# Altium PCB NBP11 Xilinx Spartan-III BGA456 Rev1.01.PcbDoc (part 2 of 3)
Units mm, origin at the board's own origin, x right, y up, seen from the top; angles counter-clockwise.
Board outline 69 x 80.99 mm, 6 copper layers (Top Layer, MidLayer1, InternalPlane1, InternalPlane2, MidLayer2, Bottom Layer); 105 components, 277 nets, 967 pads, 559 vias.
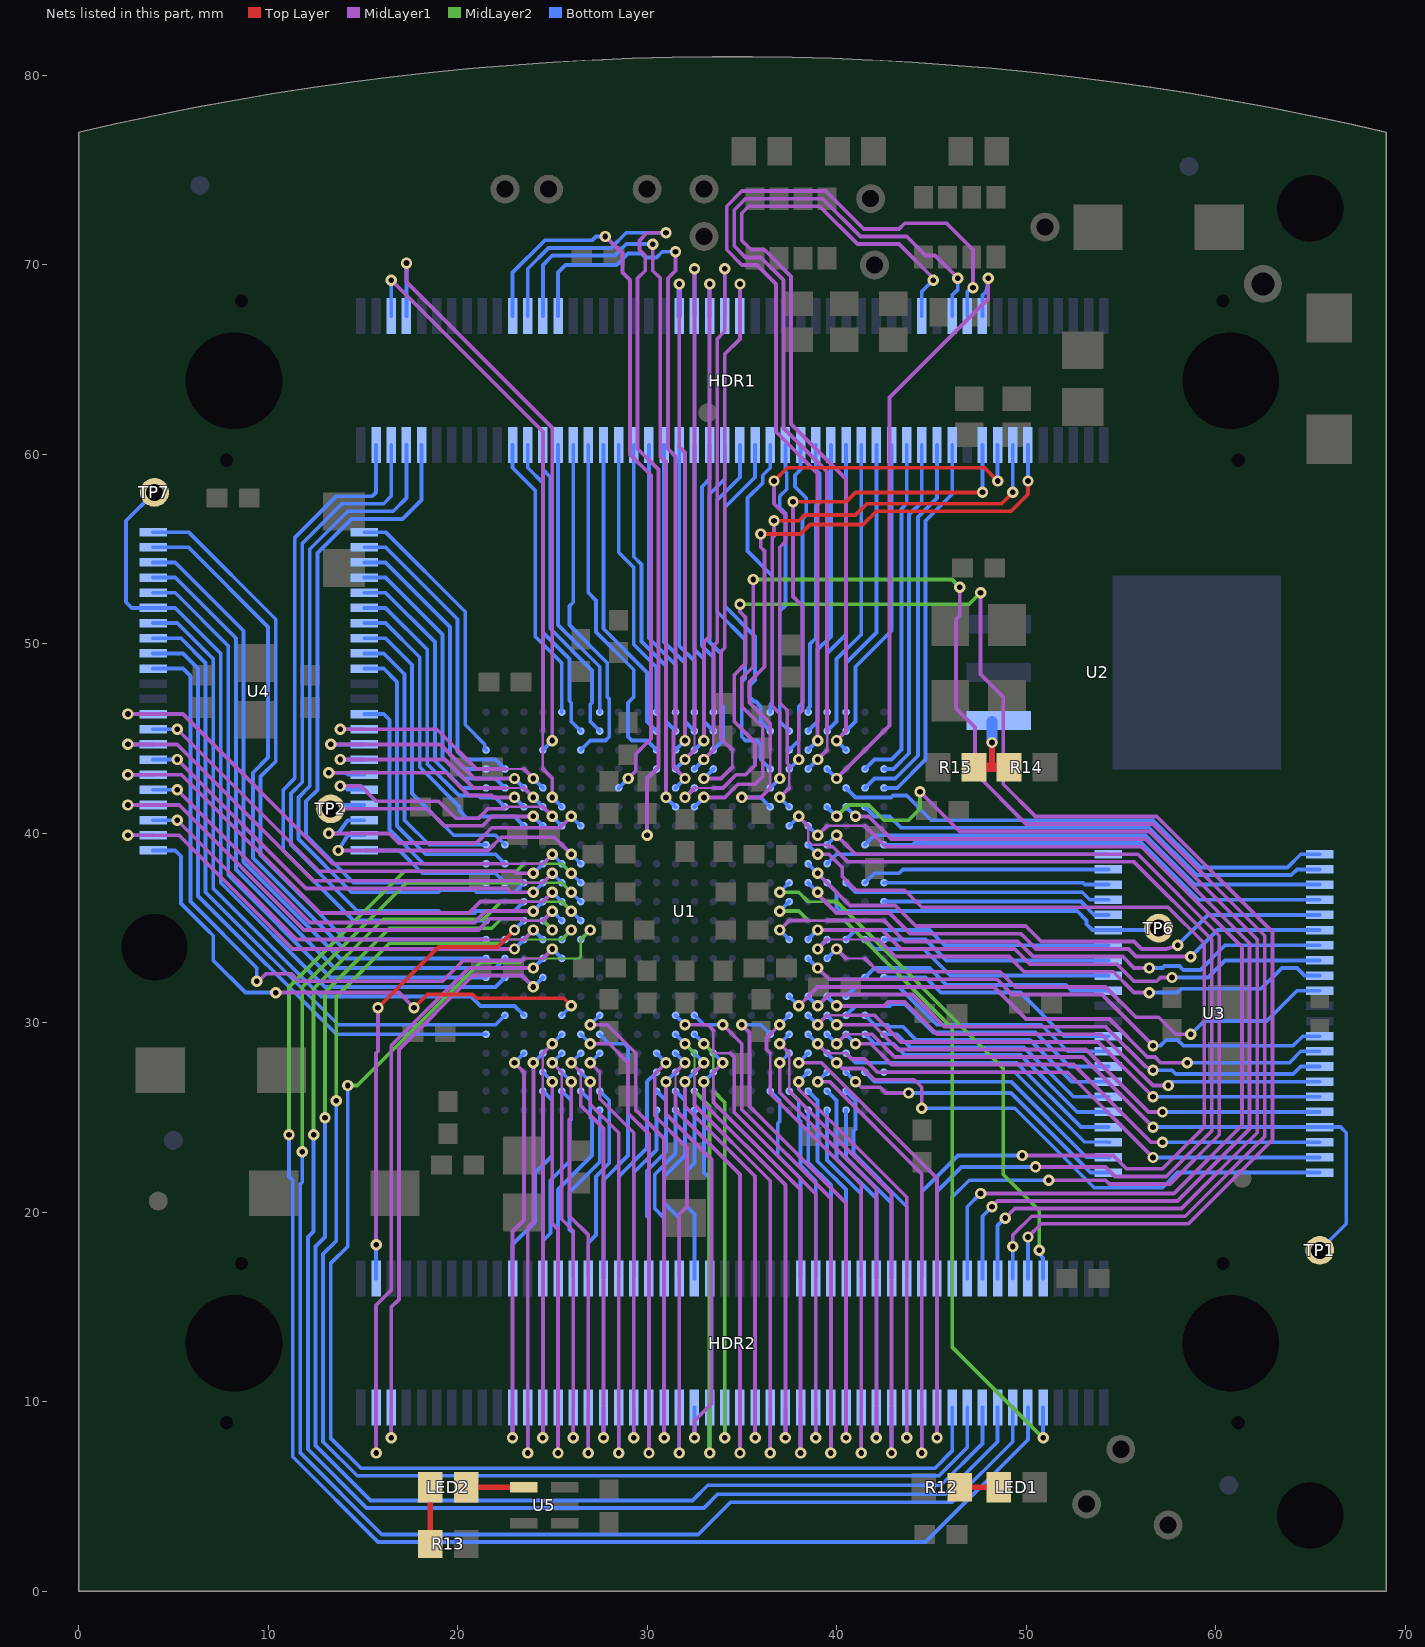
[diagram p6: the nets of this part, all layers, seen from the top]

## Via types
v1: diameter 0.6, hole 0.3, Top Layer to Bottom Layer, tented both sides, 480 vias
v2: diameter 2, hole 1.2, Top Layer to Bottom Layer, tented both sides, 42 vias
v3: diameter 0.9, hole 0.5, Top Layer to Bottom Layer, tented both sides, 33 vias
v4: diameter 0.8, hole 0.5, Top Layer to Bottom Layer, tented both sides, 2 vias
v5: diameter 1.3, hole 0.9, Top Layer to Bottom Layer, tented both sides, 1 vias
v6: diameter 1.8, hole 0.9, Top Layer to Bottom Layer, tented both sides, 1 vias

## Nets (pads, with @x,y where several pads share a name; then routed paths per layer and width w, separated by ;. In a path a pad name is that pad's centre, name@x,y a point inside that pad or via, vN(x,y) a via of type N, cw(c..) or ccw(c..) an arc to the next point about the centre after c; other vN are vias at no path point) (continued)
IO7: HDR2.21 U1.C19 | length 22.6
  MidLayer1 w0.2: v1(22.9,8.1) 22.9,19 23.5,19.6 23.5,27.4 v1(23,27.9)
  Bottom Layer w0.2: v1(22.9,8.1) HDR2.21@22.9,9.7 ; v1(23,27.9) U1.C19@23.5,28.4
IO8: HDR2.23 U1.D19 | length 23.8
  MidLayer1 w0.2: v1(23.7,7.3) 23.7,19.2 24,19.5 v1(24,27.9)
  Bottom Layer w0.2: v1(23.7,7.3) HDR2.23@23.7,9.7 ; v1(24,27.9) U1.D19@24.5,28.4
IO9: HDR2.25 U1.E18 | length 23.3
  MidLayer1 w0.127: 24.5,26.4 24.5,28.4
  MidLayer1 w0.2: v1(24.5,8.1) 24.5,26.4 ; 24.5,28.4 v1(25,28.9)
  Bottom Layer w0.2: v1(24.5,8.1) HDR2.25@24.5,9.7 ; v1(25,28.9) U1.E18@25.5,29.4
IO10: HDR2.27 U1.D20 | length 22.8
  MidLayer1 w0.2: v1(25,26.9) 25,19.4 25.3,19.1 v1(25.3,7.3)
  Bottom Layer w0.2: U1.D20@24.5,27.4 v1(25,26.9) ; v1(25.3,7.3) HDR2.27@25.3,9.7
IO11: HDR2.29 U1.E19 | length 22.6
  MidLayer1 w0.127: 25.5,26.4 25.5,27.4
  MidLayer1 w0.2: v1(25,27.9) 25.5,27.4 ; 25.5,26.4 25.5,19.634 26.1,19.034 v1(26.1,8.1)
  Bottom Layer w0.2: v1(25,27.9) U1.E19@25.5,28.4 ; v1(26.1,8.1) HDR2.29@26.1,9.7
IO12: HDR2.31 U1.E20 | length 23.2
  MidLayer1 w0.2: v1(26,26.9) 26,25 25.9,24.9 25.9,19.8 26.9,18.8 v1(26.9,7.3)
  Bottom Layer w0.2: U1.E20@25.5,27.4 v1(26,26.9) ; v1(26.9,7.3) HDR2.31@26.9,9.7
IO13: HDR2.33 U1.F19 | length 22.8
  MidLayer1 w0.127: 26.5,26.4 26.5,27.4
  MidLayer1 w0.2: v1(26,27.9) 26.5,27.4 ; 26.5,26.4 26.5,25.634 27.7,24.434 v1(27.7,8.1)
  Bottom Layer w0.2: v1(26,27.9) U1.F19@26.5,28.4 ; v1(27.7,8.1) HDR2.33@27.7,9.7
IO14: HDR2.35 U1.F20 | length 23.3
  MidLayer1 w0.2: v1(27,26.9) 27,25.7 28.5,24.2 v1(28.5,7.3)
  Bottom Layer w0.2: U1.F20@26.5,27.4 v1(27,26.9) ; v1(28.5,7.3) HDR2.35@28.5,9.7
IO15: HDR2.37 U1.G19 | length 23.1
  MidLayer1 w0.127: 27.5,26.4 27.5,27.4
  MidLayer1 w0.2: v1(27,27.9) 27.5,27.4 ; 27.5,26.4 27.5,26 29.3,24.2 v1(29.3,8.1)
  Bottom Layer w0.2: v1(27,27.9) U1.G19@27.5,28.4 ; v1(29.3,8.1) HDR2.37@29.3,9.7
IO16: HDR2.39 U1.F18 | length 26.6
  MidLayer1 w0.2: v1(27,28.9) 28,28.9 29,27.9 29,25.234 30.1,24.134 v1(30.1,7.3)
  Bottom Layer w0.2: U1.F18@26.5,29.4 v1(27,28.9) ; v1(30.1,7.3) HDR2.39@30.1,9.7
IO17: HDR2.41 U1.G17 | length 26.2
  MidLayer1 w0.2: v1(27,29.9) 27.9,29.9 29.4,28.4 29.4,25.4 30.9,23.9 v1(30.9,8.1)
  Bottom Layer w0.2: v1(27,29.9) U1.G17@27.5,30.4 ; v1(30.9,8.1) HDR2.41@30.9,9.7
IO18: HDR2.43 U1.K19 | length 24.8
  MidLayer1 w0.2: v1(31,27.9) 30.4,27.3 30.4,25.1 32.1,23.4 32.1,20.3 31.7,19.9 v1(31.7,7.3)
  Bottom Layer w0.2: U1.K19@30.5,28.4 v1(31,27.9) ; v1(31.7,7.3) HDR2.43@31.7,9.7
IO19: HDR2.45 U1.L20 | length 22.5
  MidLayer1 w0.2: v1(31,26.9) 31,25.2 33.4,22.8 33.4,9.9 32.5,9 v1(32.5,8.1)
  Bottom Layer w0.2: v1(31,26.9) U1.L20@31.5,27.4 ; v1(32.5,8.1) HDR2.45@32.5,9.7
IO20: HDR2.47 U1.L18 | length 25.2
  MidLayer2 w0.127: 32.5,26.4 32.5,28.4
  MidLayer2 w0.2: v1(32,28.9) 32.5,28.4 ; 32.5,26.4 33.3,25.6 v1(33.3,7.3)
  Bottom Layer w0.2: U1.L18@31.5,29.4 v1(32,28.9) ; v1(33.3,7.3) HDR2.47@33.3,9.7
IO21: HDR2.49 U1.M18 | length 23.6
  MidLayer2 w0.127: 33.5,26.4 33.5,28.4
  MidLayer2 w0.2: v1(33,28.9) 33.5,28.4 ; 33.5,26.4 34.1,25.8 v1(34.1,8.1)
  Bottom Layer w0.2: U1.M18@32.5,29.4 v1(33,28.9) ; v1(34.1,8.1) HDR2.49@34.1,9.7
IO22: HDR2.51 U1.L19 | length 25.3
  MidLayer1 w0.127: 31.5,26.4 31.5,27.4
  MidLayer1 w0.2: 31.5,26.4 31.5,25.4 34.9,22 v1(34.9,7.3) ; 31.5,27.4 v1(32,27.9)
  Bottom Layer w0.2: U1.L19@31.5,28.4 v1(32,27.9) ; v1(34.9,7.3) HDR2.51@34.9,9.7
IO23: HDR2.53 U1.M20 | length 22.6
  MidLayer1 w0.2: v1(32,26.9) 32,25.606 35.7,21.906 v1(35.7,8.1)
  Bottom Layer w0.2: v1(32,26.9) U1.M20@32.5,27.4 ; v1(35.7,8.1) HDR2.53@35.7,9.7
IO24: HDR2.55 U1.M19 | length 25.6
  MidLayer1 w0.127: 32.5,26.4 32.5,27.4
  MidLayer1 w0.2: 32.5,26.4 32.5,25.672 36.5,21.672 v1(36.5,7.3) ; 32.5,27.4 v1(33,27.9)
  Bottom Layer w0.2: U1.M19@32.5,28.4 v1(33,27.9) ; v1(36.5,7.3) HDR2.55@36.5,9.7
IO25: HDR2.57 U1.N20 | length 22.9
  MidLayer1 w0.2: v1(33,26.9) 33,25.737 37.3,21.437 v1(37.3,8.1)
  Bottom Layer w0.2: v1(33,26.9) U1.N20@33.5,27.4 ; v1(37.3,8.1) HDR2.57@37.3,9.7
IO26: HDR2.59 U1.N19 | length 25.8
  MidLayer1 w0.127: 33.5,26.4 33.5,27.4
  MidLayer1 w0.2: 33.5,26.4 33.5,25.803 38.1,21.203 v1(38.1,7.3) ; 33.5,27.4 v1(34,27.9)
  Bottom Layer w0.2: U1.N19@33.5,28.4 v1(34,27.9) ; v1(38.1,7.3) HDR2.59@38.1,9.7
IO27: HDR2.61 U1.L17 | length 28.3
  MidLayer1 w0.127: 33.4,29.7 33.5,29.6 33.5,28.5 33.6,28.4 34.4,28.4
  MidLayer1 w0.2: v1(32,29.9) 33.2,29.9 33.5,29.6 ; 34.4,28.4 34.6,28.2 34.6,25.269 38.9,20.969 v1(38.9,8.1)
  Bottom Layer w0.2: U1.L17@31.5,30.4 v1(32,29.9) ; v1(38.9,8.1) HDR2.61@38.9,9.7
IO28: HDR2.63 U1.M17 | length 29.1
  MidLayer1 w0.2: v1(34,29.9) 35,28.9 35,25.434 39.7,20.734 v1(39.7,7.3)
  Bottom Layer w0.2: U1.M17@32.5,30.4 33,29.9 v1(34,29.9) ; v1(39.7,7.3) HDR2.63@39.7,9.7
IO29: HDR2.65 U1.T18 | length 27.4
  MidLayer1 w0.2: v1(35,29.9) 35.4,29.5 35.4,25.6 40.5,20.5 v1(40.5,8.1)
  Bottom Layer w0.2: v1(35,29.9) 36,29.9 U1.T18@36.5,29.4 ; v1(40.5,8.1) HDR2.65@40.5,9.7
IO30: HDR2.67 U1.U17 | length 28.1
  MidLayer1 w0.127: 36.5,27.4 36.5,28.4
  MidLayer1 w0.2: 36.5,27.4 36.5,26.269 41.3,21.469 v1(41.3,7.3) ; 36.5,28.4 36.3,28.6 36.3,29.2 v1(37,29.9)
  Bottom Layer w0.2: v1(37,29.9) U1.U17@37.5,30.4 ; v1(41.3,7.3) HDR2.67@41.3,9.7
IO31: HDR2.69 U1.U19 | length 24.2
  MidLayer1 w0.2: v1(37,27.9) 37,26.334 42.1,21.234 v1(42.1,8.1)
  Bottom Layer w0.2: v1(37,27.9) U1.U19@37.5,28.4 ; v1(42.1,8.1) HDR2.69@42.1,9.7
IO32: HDR2.71 U1.U18 | length 27.2
  MidLayer1 w0.127: 37.5,26.4 37.5,28.4
  MidLayer1 w0.2: v1(37,28.9) 37.5,28.4 ; 37.5,26.4 42.9,21 v1(42.9,7.3)
  Bottom Layer w0.2: v1(37,28.9) U1.U18@37.5,29.4 ; v1(42.9,7.3) HDR2.71@42.9,9.7
IO33: HDR2.73 U1.V20 | length 23.5
  MidLayer1 w0.2: v1(38,26.9) 38,26.5 43.7,20.8 v1(43.7,8.1)
  Bottom Layer w0.2: v1(38,26.9) U1.V20@38.5,27.4 ; v1(43.7,8.1) HDR2.73@43.7,9.7
IO34: HDR2.75 U1.W20 | length 25.4
  MidLayer1 w0.2: v1(39,26.9) 39.634,26.9 44.5,22.034 v1(44.5,7.3)
  Bottom Layer w0.2: v1(39,26.9) U1.W20@39.5,27.4 ; v1(44.5,7.3) HDR2.75@44.5,9.7
IO35: HDR2.77 U1.V19 | length 25.8
  MidLayer1 w0.2: v1(38,27.9) 39.2,27.9 45.3,21.8 v1(45.3,8.1)
  Bottom Layer w0.2: v1(38,27.9) U1.V19@38.5,28.4 ; v1(45.3,8.1) HDR2.77@45.3,9.7
JIOA0: HDR1.3 U1.A12 | length 36.8
  Bottom Layer w0.2: HDR1.3@15.7,60.5 15.7,58 15.5,57.8 13.6,57.8 11.4,55.6 11.4,42.9 10.8,42.3 10.8,39.1 14.5,35.4 21,35.4 U1.A12@21.5,35.4
JIOA1: HDR1.5 U1.C11 | length 38.6
  Bottom Layer w0.2: HDR1.5@16.5,60.5 16.5,57.8 16.1,57.4 13.9,57.4 11.8,55.3 11.8,42.7 11.2,42.1 11.2,39.4 14.7,35.9 19,35.9 19.1,35.8 20.9,35.8 21,35.9 23,35.9 U1.C11@23.5,36.4
JIOA2: HDR1.7 U1.C10 | length 37.9
  Bottom Layer w0.2: HDR1.7@17.3,60.5 17.3,57.7 16.6,57 14.2,57 12.2,55 12.2,42.5 11.6,41.9 11.6,39.7 14.4,36.9 19,36.9 19.1,37 20.9,37 21,36.9 23,36.9 U1.C10@23.5,37.4
JIOA3: HDR1.9 U1.A10 | length 35.2
  Bottom Layer w0.2: HDR1.9@18.1,60.5 18.1,57.6 17.1,56.6 14.4,56.6 12.6,54.8 12.6,42.3 12,41.7 12,39.9 14.5,37.4 U1.A10@21.5,37.4
JIOB0: HDR1.83 U1.U4 | length 27.3
  Top Layer w0.2: v1(37.7,57.5) 40.5,57.5 41,58 v1(47.7,58)
  MidLayer1 w0.2: v1(37.7,57.5) 37.7,52.5 38.2,52 38.2,46.5 38,46.3 v1(38,43.9)
  Bottom Layer w0.2: U1.U4@37.5,43.4 v1(38,43.9) ; v1(47.7,58) HDR1.83@47.7,60.5
JIOB1: HDR1.85 U1.U6 | length 32.5
  Top Layer w0.2: v1(36.7,58.6) 37.4,59.3 47.8,59.3 v1(48.5,58.6)
  MidLayer1 w0.127: 37.5,42.4 37.5,43.4
  MidLayer1 w0.2: v1(36.7,58.6) 36.7,57.4 37.3,56.8 37.3,55.4 37,55.1 37,46.9 37.4,46.5 37.4,43.7 37.5,43.6 37.5,43.4 ; v1(37,41.9) 37.5,42.4
  Bottom Layer w0.2: v1(37,41.9) U1.U6@37.5,41.4 ; v1(48.5,58.6) HDR1.85@48.5,60.5
JIOB2: HDR1.87 U1.T5 | length 30.2
  Top Layer w0.2: v1(36.7,56.5) 38,56.5 38.3,56.8 41,56.8 41.6,57.4 48.7,57.4 v1(49.3,58)
  MidLayer1 w0.2: v1(36.7,56.5) 36.7,55.7 36.6,55.6 36.6,46.734 37,46.334 v1(37,42.9)
  Bottom Layer w0.2: U1.T5@36.5,42.4 36.55,42.45 v1(37,42.9) ; v1(49.3,58) HDR1.87@49.3,60.5
JIOB3: HDR1.89 U1.T6 | length 35.3
  Top Layer w0.2: v1(36,55.8) 38.1,55.8 38.6,56.3 41.4,56.3 42.1,57 49.2,57 50.1,57.9 v1(50.1,58.6)
  MidLayer1 w0.127: 36.5,42.4 36.5,44.4
  MidLayer1 w0.2: v1(35,41.9) 36,41.9 36.5,42.4 ; v1(36,55.8) 36,55.1 36.2,54.9 36.2,48.8 35.4,48 35.4,46.9 36.5,45.8 36.5,44.4
  Bottom Layer w0.2: v1(35,41.9) 36,41.9 U1.T6@36.5,41.4 ; v1(50.1,58.6) HDR1.89@50.1,60.5
KBCLOCK: HDR1.22 U1.H5 | length 38.8
  MidLayer1 w0.2: v1(27.8,71.5) 28.7,70.6 28.7,69.6 29.1,69.2 29.1,60 30.2,58.9 30.2,45 29.4,44.2 29.4,43.3 v1(29,42.9)
  Bottom Layer w0.2: HDR1.22@22.9,67.3 22.9,69.6 24.6,71.3 27.1,71.3 27.3,71.5 v1(27.8,71.5) ; U1.H5@28.5,42.4 v1(29,42.9)
KBDATA: HDR1.24 U1.K4 | length 48.3
  MidLayer1 w0.2: v1(30,39.9) 30,42.9 30.6,43.5 30.6,59.2 29.5,60.3 29.5,69.3 29.9,69.7 29.9,70.5 29.6,70.8 29.6,71.3 30,71.7 v1(31,71.7)
  Bottom Layer w0.2: HDR1.24@23.7,67.3 23.7,69.8 24.8,70.9 28.1,70.9 28.9,71.7 v1(31,71.7) ; v1(30,39.9) 30,42.9 U1.K4@30.5,43.4
LCD_BCKL: HDR2.22 U1.D21 | length 11.1
  Bottom Layer w0.2: HDR2.22@22.9,16.4 HDR2.22@22.9,16.5 22.9,18.3 24.1,19.5 24.1,22.1 25,23 25,25.9 U1.D21@24.5,26.4
LCD_E: HDR2.26 U1.E21 | length 10.7
  Bottom Layer w0.2: HDR2.26@24.5,16.5 24.5,18.5 24.9,18.9 24.9,21.7 25.9,22.7 25.9,24.8 26,24.9 26,25.9 U1.E21@25.5,26.4
LED0: HDR2.60 U1.T21 | length 10.6
  Bottom Layer w0.2: U1.T21@36.5,26.4 37,25.9 37,24.8 36.9,24.7 36.9,23 38.1,21.8 HDR2.60@38.1,16.5
LED1: HDR2.62 U1.U21 | length 10.5
  Bottom Layer w0.2: U1.U21@37.5,26.4 38,25.9 38,24.9 38.1,24.8 38.1,22.472 38.9,21.672 HDR2.62@38.9,16.5
LED2: HDR2.64 U1.V22 | length 9.4
  Bottom Layer w0.2: U1.V22@38.5,25.4 38.5,22.637 39.7,21.437 HDR2.64@39.7,16.5
LED3: HDR2.66 U1.V21 | length 10.7
  Bottom Layer w0.2: U1.V21@38.5,26.4 39,25.9 39,22.703 40.5,21.203 HDR2.66@40.5,16.5
LED4: HDR2.68 U1.W22 | length 9.6
  Bottom Layer w0.2: U1.W22@39.5,25.4 39.5,22.769 41.3,20.969 HDR2.68@41.3,16.5
LED5: HDR2.70 U1.W21 | length 11
  Bottom Layer w0.2: U1.W21@39.5,26.4 40,25.9 40,22.834 42.1,20.734 HDR2.70@42.1,16.5
LED6: HDR2.72 U1.Y22 | length 9.9
  Bottom Layer w0.2: U1.Y22@40.5,25.4 40.5,22.9 42.9,20.5 HDR2.72@42.9,16.5
LED7: HDR2.74 U1.Y21 | length 11.3
  Bottom Layer w0.2: U1.Y21@40.5,26.4 41,25.9 41,24.4 40.9,24.3 40.9,23.1 43.7,20.3 HDR2.74@43.7,16.5
MOUSECLOCK: HDR1.26 U1.L6 | length 39.4
  MidLayer1 w0.2: v1@30.4,70.946 v1@30.3,71.046 ; v1(31,41.9) 31,59.6 30.7,59.9 30.7,69.3 30.3,69.7 v1@30.3,71.046 ; v1@30.3,71.046 30.273,71.073 30.246,71.1 v1(30.3,71.1) v1@30.3,71.046
  Bottom Layer w0.2: HDR1.26@24.5,67.3 24.5,70 24.998,70.498 28.298,70.498 28.9,71.1 v1(30.3,71.1) ; v1(31,41.9) U1.L6@31.5,41.4
MOUSEDATA: HDR1.28 U1.L5 | length 38.2
  MidLayer1 w0.2: v1(31.5,70.7) 31.5,69.7 31.1,69.3 31.1,60.3 31.5,59.9 31.5,45.4 31.4,45.3 31.4,43.5 v1(32,42.9)
  Bottom Layer w0.2: HDR1.28@25.3,67.3 25.3,69.6 25.7,70 28.4,70 29,70.6 29.7,70.6 29.9,70.4 30.5,70.4 30.8,70.7 v1(31.5,70.7) ; U1.L5@31.5,42.4 v1(32,42.9)
NetLED1_1: LED1.1 R12.2 | length 2.1
  Top Layer w0.3: R12.2@46.5,5.5 LED1.1@48.55,5.5
NetLED2_1: LED2.1 R13.1 | length 3
  Top Layer w0.3: R13.1@18.55,2.5 LED2.1@18.55,5.5
NetLED2_2: LED2.2 U5.4 | length 3
  Top Layer w0.3: LED2.2@20.45,5.5 U5.4@23.5,5.5
NetR14_2: R14.2 R15.1 U2.1 | length 4.3
  Top Layer w0.3: 48.2,43.5 v1(48.2,44.8)
  Top Layer w0.5: R15.1@47.25,43.5 48.2,43.5 R14.2@49.1,43.5
  Bottom Layer w0.5: v1@48.15,44.95 v1@48.2,45
  Bottom Layer w0.6: v1(48.2,44.8) 48.2,45 U2.1@48.2,45.9
NEXUS_TCK: HDR1.82 U1.V3 | length 50
  MidLayer1 w0.2: v1(39,44.9) 39,59 36.8,61.2 36.8,69 35.8,70 35,70 34.2,70.8 34.2,73.1 35,73.9 39.431,73.9 41.431,71.9 41.7,71.9 ; 41.6,71.9 43.3,71.9 43.6,72.2 45.8,72.2 47.2,70.8 v1(47.2,68.8)
  Bottom Layer w0.2: U1.V3@38.5,44.4 v1(39,44.9) ; HDR1.82@46.9,67.3 46.9,68.6 v1(47.2,68.8)
NEXUS_TDI: HDR1.84 U1.W4 | length 32.5
  MidLayer1 w0.2: v1(40,42.9) 42.8,45.7 42.8,63 48,68.2 v1(48,69.3)
  Bottom Layer w0.2: U1.W4@39.5,43.4 v1(40,42.9) ; HDR1.84@47.7,67.3 47.7,68.4 47.9,68.6 v1(48,69.3)
NEXUS_TDO: HDR1.76 U1.Y3 | length 45.5
  MidLayer1 w0.2: v1(40,44.9) 40.5,45.4 40.5,58.7 37.6,61.6 37.6,69.4 36.2,70.8 35.5,70.8 35,71.3 35,72.7 35,72.734 35.366,73.1 39.1,73.1 41.1,71.1 43.3,71.1 45.1,69.3 v1(45.1,69.2)
  Bottom Layer w0.2: v1(40,44.9) U1.Y3@40.5,44.4 ; HDR1.76@44.5,67.3 44.5,68.6 v1(45.1,69.2)
NEXUS_TMS: HDR1.80 U1.V4 | length 48.3
  MidLayer1 w0.127: 39.5,44.4 39.5,45.4
  MidLayer1 w0.2: v1(39,43.9) 39.5,44.4 ; 39.5,45.4 39.5,59.1 37.2,61.4 37.2,69.2 36,70.4 35.2,70.4 34.6,71 34.6,72.9 35.2,73.5 39.266,73.5 41.266,71.5 43.7,71.5 44.7,70.5 45.2,70.5 v1(46.4,69.3)
  Bottom Layer w0.2: U1.V4@38.5,43.4 v1(39,43.9) ; HDR1.80@46.1,67.3 46.1,68.4 46.4,68.7 v1(46.4,69.3)
RAM0_DATA0: HDR2.42 U1.L22 | length 9.6
  Bottom Layer w0.2: HDR2.42@30.9,16.5 30.9,19.7 30.4,20.2 30.4,22 31.5,23.1 U1.L22@31.5,25.4
RAM0_DATA1: HDR2.40 U1.K21 | length 10.6
  Bottom Layer w0.2: HDR2.40@30.1,16.5 30.1,19.7 30,19.8 30,22.2 31,23.2 31,25.9 U1.K21@30.5,26.4
RAM0_DATA2: HDR2.38 U1.K22 | length 9.4
  Bottom Layer w0.2: HDR2.38@29.3,16.5 29.3,22.1 30.5,23.3 U1.K22@30.5,25.4
RAM0_DATA3: HDR2.36 U1.K20 | length 11.7
  Bottom Layer w0.2: HDR2.36@28.5,16.5 28.5,21.9 30,23.4 30,26.9 U1.K20@30.5,27.4
RAM0_DATA4: HDR2.34 U1.G18 | length 14.5
  Bottom Layer w0.2: U1.G18@27.5,29.4 28,28.9 28.8,28.9 29,28.7 29,23 27.7,21.7 HDR2.34@27.7,16.5
RAM0_DATA5: HDR2.32 U1.G21 | length 10.6
  Bottom Layer w0.2: HDR2.32@26.9,16.5 26.9,18.4 27.3,18.8 27.3,21.9 28,22.6 28,25.9 U1.G21@27.5,26.4
RAM0_DATA6: HDR2.30 U1.G22 | length 9.6
  Bottom Layer w0.2: HDR2.30@26.1,16.5 26.1,18.9 25.9,19.1 25.9,21.066 27.5,22.666 U1.G22@27.5,25.4
RAM0_DATA7: HDR2.28 U1.F21 | length 10.9
  Bottom Layer w0.2: HDR2.28@25.3,16.5 25.3,21.2 27.1,23 27.1,24.9 27,25 27,25.9 U1.F21@26.5,26.4
RAM0_OE: HDR1.41 U1.M2 | length 15.8
  Bottom Layer w0.2: HDR1.41@30.9,60.5 30.9,50.1 32,49 32,45.9 U1.M2@32.5,45.4
RAM0_WE: HDR1.79 U1.AB5 | length 20
  Bottom Layer w0.2: U1.AB5@42.5,42.4 43.2,42.4 44.7,43.9 44.7,56.5 46.1,57.9 HDR1.79@46.1,60.5
RAM1_DATA0: HDR1.45 U1.N2 | length 15.5
  Bottom Layer w0.2: HDR1.45@32.5,60.5 32.5,49.7 33,49.2 33,45.9 U1.N2@33.5,45.4
RAM1_DATA1: HDR1.49 U1.N3 | length 16.9
  Bottom Layer w0.2: U1.N3@33.5,44.4 34,44.9 34,46.7 33.9,46.8 33.9,49.5 33.3,50.1 33.3,57.9 34.1,58.7 HDR1.49@34.1,60.5
RAM1_DATA2: HDR1.53 U1.T2 | length 17.1
  Bottom Layer w0.2: HDR1.53@35.7,60.5 35.7,58.8 34.1,57.2 34.1,52 35.7,50.4 35.7,48.1 35.4,47.8 35.4,47.2 35.641,46.959 35.741,46.959 36,46.7 36,45.9 U1.T2@36.5,45.4
RAM1_DATA3: HDR1.57 U1.U2 | length 15.7
  Bottom Layer w0.2: HDR1.57@37.3,60.5 37.3,59.1 37.367,59.033 37.367,58.167 37,57.8 37,57.2 37.3,56.9 37.3,52.025 37,51.725 37,45.9 U1.U2@37.5,45.4
RAM1_DATA4: HDR1.55 U1.T1 | length 15.2
  Bottom Layer w0.2: U1.T1@36.5,46.4 36.5,46.8 36.6,46.9 36.6,53.6 35.3,54.9 35.3,57.7 36.1,58.5 36.1,58.9 36.5,59.3 HDR1.55@36.5,60.5
RAM1_DATA5: HDR1.51 U1.T4 | length 19.2
  Bottom Layer w0.2: HDR1.51@34.9,60.5 34.9,58.8 33.7,57.6 33.7,51.7 35.17,50.23 35.17,48.17 35,48 35,45.1 35.2,44.9 35.8,44.9 36,44.7 36,43.9 U1.T4@36.5,43.4
RAM1_DATA6: HDR1.47 U1.N1 | length 14.5
  Bottom Layer w0.2: HDR1.47@33.3,60.5 33.3,58.7 32.9,58.3 32.9,49.9 33.3,49.5 33.5,49.3 U1.N1@33.5,46.4
RAM1_DATA7: HDR1.43 U1.M1 | length 14.4
  Bottom Layer w0.2: HDR1.43@31.7,60.5 31.7,49.9 32.5,49.1 U1.M1@32.5,46.4
RAM1_OE: HDR1.39 U1.L1 | length 14.7
  Bottom Layer w0.2: HDR1.39@30.1,60.5 30.1,50.3 31.5,48.9 U1.L1@31.5,46.4
RAM1_WE: HDR1.61 U1.V1 | length 14.4
  Bottom Layer w0.2: U1.V1@38.5,46.4 38.5,46.6 38.6,46.7 38.6,50 38.9,50.3 38.9,57.3 39.1,57.5 39.1,59 38.9,59.2 HDR1.61@38.9,60.5
RAM_ADDR0: HDR1.21 U1.E1 | length 15.2
  Bottom Layer w0.2: HDR1.21@22.9,60.5 22.9,59.3 24.1,58.1 24.1,50.4 25.5,49 U1.E1@25.5,46.4
RAM_ADDR1: HDR1.25 U1.G2 | length 16.4
  Bottom Layer w0.2: HDR1.25@24.5,60.5 24.5,59.2 24.9,58.8 24.9,50.8 27.1,48.6 27.1,46.9 27,46.8 27,45.9 U1.G2@27.5,45.4
RAM_ADDR2: HDR1.29 U1.F3 | length 18.1
  Bottom Layer w0.2: HDR1.29@26.1,60.5 26.1,52.2 25.9,52 25.9,51 27.9,49 27.9,47.2 28,47.1 28,45.1 27.8,44.9 27,44.9 U1.F3@26.5,44.4
RAM_ADDR3: HDR1.33 U1.K2 | length 16.3
  Bottom Layer w0.2: HDR1.33@27.7,60.5 27.7,50.8 30,48.5 30,45.9 U1.K2@30.5,45.4
RAM_ADDR4: HDR1.65 U1.W1 | length 14.5
  Bottom Layer w0.2: U1.W1@39.5,46.4 39.5,49.5 40.5,50.5 HDR1.65@40.5,60.5
RAM_ADDR5: HDR1.69 U1.Y1 | length 14.8
  Bottom Layer w0.2: U1.Y1@40.5,46.4 40.5,49 42.1,50.6 HDR1.69@42.1,60.5
RAM_ADDR6: HDR1.73 U1.AA4 | length 18.5
  Bottom Layer w0.2: U1.AA4@41.5,43.4 42,43.9 42.9,43.9 43.427,44.427 43.427,57.127 43.7,57.4 HDR1.73@43.7,60.5
RAM_ADDR7: HDR1.77 U1.AA5 | length 20.3
  Bottom Layer w0.2: U1.AA5@41.5,42.4 42,42.9 43.1,42.9 44.3,44.1 44.3,56.7 45.3,57.7 HDR1.77@45.3,60.5
RAM_ADDR8: HDR1.75 U1.AB4 | length 18.2
  Bottom Layer w0.2: U1.AB4@42.5,43.4 43,43.4 43.827,44.227 43.827,56.827 44.5,57.5 HDR1.75@44.5,60.5
RAM_ADDR9: HDR1.71 U1.Y2 | length 16.1
  Bottom Layer w0.2: U1.Y2@40.5,45.4 41,45.9 41,48.8 42.9,50.7 HDR1.71@42.9,60.5
RAM_ADDR10: HDR1.67 U1.W2 | length 15.8
  Bottom Layer w0.2: U1.W2@39.5,45.4 40,45.9 40,49.2 41.3,50.5 HDR1.67@41.3,60.5
RAM_ADDR11: HDR1.63 U1.V2 | length 15.6
  Bottom Layer w0.2: U1.V2@38.5,45.4 39,45.9 39,49.7 39.7,50.4 HDR1.63@39.7,60.5
RAM_ADDR12: HDR1.59 U1.U3 | length 16.8
  Bottom Layer w0.2: U1.U3@37.5,44.4 38,44.9 38,46.7 38.2,46.9 38.2,56.6 38.4,56.8 38.4,57.7 37.8,58.3 37.8,58.9 38.1,59.2 HDR1.59@38.1,60.5
RAM_ADDR13: HDR1.35 U1.K1 | length 14.9
  Bottom Layer w0.2: HDR1.35@28.5,60.5 28.5,54.834 29.3,54.034 29.3,49.969 30.5,48.769 U1.K1@30.5,46.4
RAM_ADDR14: HDR1.31 U1.K3 | length 18.3
  Bottom Layer w0.2: HDR1.31@26.9,60.5 26.9,52.7 27.3,52.3 27.3,50.634 29.3,48.634 29.3,47.2 29,46.9 29,45.1 29.2,44.9 30,44.9 U1.K3@30.5,44.4
RAM_ADDR15: HDR1.27 U1.G1 | length 15
  Bottom Layer w0.2: HDR1.27@25.3,60.5 25.3,51 27.5,48.8 U1.G1@27.5,46.4
RAM_ADDR16: HDR1.23 U1.F2 | length 16.3
  Bottom Layer w0.2: HDR1.23@23.7,60.5 23.7,59.3 24.5,58.5 24.5,50.6 25.9,49.2 25.9,47 26,46.9 26,45.9 U1.F2@26.5,45.4
RAM_CS: HDR1.37 U1.L2 | length 16
  Bottom Layer w0.2: HDR1.37@29.3,60.5 29.3,54.6 29.7,54.2 29.7,50.134 31,48.834 31,45.9 U1.L2@31.5,45.4
RED0: HDR1.6 U1.E6 | length 33.4
  MidLayer1 w0.127: 24.5,43.4 24.5,45.4
  MidLayer1 w0.2: v1(16.5,69.2) 24.5,61.2 24.5,45.4 ; 24.5,43.4 25,42.9 v1(25,41.9)
  Bottom Layer w0.2: HDR1.6@16.5,67.3 v1(16.5,69.2) ; v1(25,41.9) 25.45,41.45 U1.E6@25.5,41.4
RED1: HDR1.8 U1.D3 | length 31.9
  MidLayer1 w0.2: v1(17.3,70.1) 17.3,69.1 25,61.4 v1(25,44.9)
  Bottom Layer w0.2: HDR1.8@17.3,67.3 v1(17.3,70.1) ; U1.D3@24.5,44.4 v1(25,44.9)
REF_CLK: HDR2.4 U1.C12 | length 23.9
  Top Layer w0.2: v1(15.8,30.8) 19,34 22.1,34 v1(23,34.9)
  MidLayer1 w0.2: v1(15.7,18.3) 15.7,28.4 15.8,28.5 v1(15.8,30.8)
  Bottom Layer w0.2: HDR2.4@15.7,16.5 v1(15.7,18.3) ; v1(23,34.9) U1.C12@23.5,35.4
SCL: HDR2.5 U1.D15 | length 31.9
  MidLayer1 w0.2: v1(16.5,8.1) 16.5,15 16.9,15.4 16.9,28.6 20.8,32.5 23.4,32.5 v1(24,31.9)
  Bottom Layer w0.2: v1(16.5,8.1) HDR2.5@16.5,9.7 ; v1(24,31.9) U1.D15@24.5,32.4
SDA: HDR2.3 U1.D14 | length 34.1
  MidLayer1 w0.2: v1(15.7,7.3) 15.7,15.1 16.5,15.9 16.5,28.8 20.6,32.9 v1(24,32.9)
  Bottom Layer w0.2: v1(15.7,7.3) HDR2.3@15.7,9.7 ; v1(24,32.9) U1.D14@24.5,33.4
SP0: HDR2.79 U1.F13 | length 72.5
  MidLayer2 w0.127: 23.5,33.4 26.4,33.4 26.5,33.5 26.5,34.4
  MidLayer2 w0.2: v1(14.2,26.7) 14.7,26.7 21.2,33.2 23.3,33.2 23.5,33.4 ; 26.5,34.4 v1(27,34.9)
  Bottom Layer w0.2: v1(14.2,26.7) 14.2,18.2 13.3,17.3 13.3,8.1 14.9,6.5 45.2,6.5 46.1,7.4 HDR2.79@46.1,9.7 ; U1.F13@26.5,34.4 26.55,34.45 v1(27,34.9)
SP1: HDR2.81 U1.E13 | length 75.8
  MidLayer2 w0.127: 22.5,34.4 25.5,34.4
  MidLayer2 w0.2: v1(13.6,25.9) 13.6,31.4 16.4,34.2 22.3,34.2 22.5,34.4 ; 25.5,34.4 v1(26,34.9)
  Bottom Layer w0.2: v1(13.6,25.9) 13.6,18.5 12.9,17.8 12.9,7.9 14.7,6.1 45.4,6.1 46.9,7.6 HDR2.81@46.9,9.7 ; U1.E13@25.5,34.4 25.55,34.45 v1(26,34.9)
SP2: HDR2.83 U1.D12 | length 78.2
  MidLayer2 w0.127: 23.5,35.4 24.5,35.4
  MidLayer2 w0.2: v1(13,25) 13,31.6 16.4,35 21.8,35 22.3,35.5 23.4,35.5 23.5,35.4 ; 24.5,35.4 v1(25,34.9)
  Bottom Layer w0.2: v1(13,25) 13,18.7 12.5,18.2 12.5,7.7 15.4,4.8 32.4,4.8 33.2,5.6 45.5,5.6 47.7,7.8 HDR2.83@47.7,9.7 ; U1.D12@24.5,35.4 v1(25,34.9)
SP3: HDR2.85 U1.F12 | length 81.8
  MidLayer2 w0.127: 23.5,36.4 25.5,36.4
  MidLayer2 w0.2: v1(12.4,24.1) 12.4,31.8 16.073,35.473 21.373,35.473 22.3,36.4 23.5,36.4 ; 25.5,36.4 v1(26,35.9)
  Bottom Layer w0.2: v1(12.4,24.1) 12.4,19 12.1,18.7 12.1,7.5 15.2,4.4 33,4.4 33.723,5.123 45.723,5.123 48.5,7.9 HDR2.85@48.5,9.7 ; v1(26,35.9) U1.F12@26.5,35.4
SP4: HDR2.87 U1.F11 | length 85.2
  MidLayer2 w0.127: 23.5,37.4 25.5,37.4
  MidLayer2 w0.2: v1(11.8,23.2) 11.8,31.9 17.3,37.4 23.5,37.4 ; 25.5,37.4 v1(26,36.9)
  Bottom Layer w0.2: v1(11.8,23.2) 11.8,21.6 11.7,21.5 11.7,7.3 16,3 32.7,3 34.4,4.7 46.1,4.7 49.3,7.9 HDR2.87@49.3,9.7 ; v1(26,36.9) 26.45,36.45 U1.F11@26.5,36.4
SP5: HDR2.89 U1.F10 | length 88
  MidLayer2 w0.127: 23.5,38.4 25.5,38.4
  MidLayer2 w0.2: v1(11.1,24.1) 11.1,31.9 17.2,38 23.1,38 23.5,38.4 ; 25.5,38.4 v1(26,37.9)
  Bottom Layer w0.2: v1(11.1,24.1) 11.1,21.9 11.3,21.7 11.3,7.1 15.8,2.6 44.7,2.6 50.1,8 HDR2.89@50.1,9.7 ; v1(26,37.9) U1.F10@26.5,37.4
SP6: HDR2.91 U1.U11 | length 37.6
  MidLayer2 w0.127: 38.5,35.4 39.5,35.4
  MidLayer2 w0.2: v1(37,35.9) 38,35.9 38.5,35.4 ; 39.5,35.4 40.434,35.4 46.1,29.734 46.1,12.9 v1(50.9,8.1)
  Bottom Layer w0.2: v1(37,35.9) U1.U11@37.5,36.4 ; v1(50.9,8.1) HDR2.91@50.9,9.7
SP7: HDR2.90 U1.M5 | length 83.6
  MidLayer1 w0.127: 32.5,42.4 33.5,42.4
  MidLayer1 w0.2: v1(32,41.9) 32.5,42.4 ; 33.5,42.4 34,42.4 34.7,43.1 35.2,43.1 35.7,43.6 35.7,44.8 34.6,45.9 34.6,48.366 35.2,48.966 35.2,51.4 34.9,51.7 v1(34.9,52.1) ; v1(47.6,52.7) 47.6,48.4 48.8,47.2 48.8,42.6 50.5,40.9 56.9,40.9 63,34.8 63,23.834 58.566,19.4 57.9,19.4 50.8,19.4 v1(50.1,18.7)
  MidLayer2 w0.2: v1(34.9,52.1) 47,52.1 v1(47.6,52.7)
  Bottom Layer w0.2: v1(32,41.9) U1.M5@32.5,42.4 ; HDR2.90@50.1,16.5 50.1,18.3 v1(50.1,18.7)
SP8: HDR2.92 U1.U10 | length 28.3
  MidLayer2 w0.127: 38.5,36.4 39.5,36.4
  MidLayer2 w0.2: v1(37,36.9) 38,36.9 38.5,36.4 ; 39.5,36.4 40,36.4 48.8,27.6 48.8,22 50.7,20.1 v1(50.7,18)
  Bottom Layer w0.2: v1(37,36.9) U1.U10@37.5,37.4 ; v1(50.7,18) 50.7,17.8 50.9,17.6 HDR2.92@50.9,16.5
SP9: HDR2.88 U1.M6 | length 83.9
  MidLayer1 w0.2: v1(33,41.9) 34,41.9 34.1,41.9 34.8,42.6 35.7,42.6 36.1,43 36.1,43.6 36.1,45.6 35,46.7 35,48.2 35.6,48.8 v1(35.6,53.4) ; v1(46.5,53) 46.5,51.5 46.3,51.3 46.3,46.6 47.3,45.6 47.3,43.2 50,40.5 56.7,40.5 62.6,34.6 62.6,24 58.4,19.8 50.3,19.8 49.3,18.8 v1(49.3,18.2)
  MidLayer2 w0.2: v1(35.6,53.4) 46.1,53.4 v1(46.5,53)
  Bottom Layer w0.2: U1.M6@32.5,41.4 v1(33,41.9) ; HDR2.88@49.3,16.5 v1(49.3,18.2)
SP10: HDR2.86 U1.W6 | length 56.6
  MidLayer1 w0.2: v1(44.4,42.2) 46.5,40.1 56.5,40.1 62.2,34.4 62.2,24.2 58.2,20.2 49.4,20.2 v1(48.9,19.7)
  MidLayer2 w0.2: v1(40,40.9) 40.6,41.5 41.7,41.5 42.5,40.7 43.8,40.7 44.4,41.3 v1(44.4,42.2)
  Bottom Layer w0.2: U1.W6@39.5,41.4 v1(40,40.9) ; HDR2.86@48.5,16.5 48.5,19.3 v1(48.9,19.7)
SP11: HDR2.84 U1.Y6 | length 53.4
  MidLayer1 w0.2: v1(41,40.9) 41.7,40.9 42.9,39.7 56.3,39.7 61.8,34.2 61.8,24.4 58,20.6 48.5,20.6 v1(48.2,20.3)
  Bottom Layer w0.2: U1.Y6@40.5,41.4 v1(41,40.9) ; HDR2.84@47.7,16.5 47.7,19.8 v1(48.2,20.3)
SP12: HDR2.82 U1.V7 | length 55.4
  MidLayer1 w0.127: 39.5,40.4 41.5,40.4
  MidLayer1 w0.2: v1(39,39.9) 39.5,40.4 ; 41.5,40.4 42.6,39.3 56.1,39.3 61.4,34 61.4,24.6 57.8,21 v1(47.6,21)
  Bottom Layer w0.2: U1.V7@38.5,40.4 v1(39,39.9) ; HDR2.82@46.9,16.5 46.9,20.3 v1(47.6,21)
SP13: HDR2.80 U1.W8 | length 53.5
  MidLayer1 w0.2: v1(40,39.9) 41,38.9 42,38.9 55.9,38.9 60.2,34.6 60.2,24.1 57.6,21.5 54.4,21.5 54.2,21.7 v1(51.2,21.7)
  Bottom Layer w0.2: U1.W8@39.5,39.4 v1(40,39.9) ; HDR2.80@46.1,16.5 46.1,20.8 47,21.7 v1(51.2,21.7)
SP14: HDR2.78 U1.U7 | length 56.7
  MidLayer1 w0.127: 38.5,40.4 38.5,39.6 38.7,39.4 39.5,39.4
  MidLayer1 w0.2: v1(38,40.9) 38.5,40.4 ; 39.5,39.4 39.6,39.3 39.8,39.3 40.6,38.5 55.7,38.5 59.8,34.4 59.8,24.3 57.4,21.9 54.7,21.9 54.2,22.4 v1(50.5,22.4)
  Bottom Layer w0.2: U1.U7@37.5,40.4 v1(38,40.9) ; HDR2.78@45.3,16.4 HDR2.78@45.3,16.5 45.3,21.1 46.6,22.4 v1(50.5,22.4)
SP15: HDR2.76 U1.V8 | length 54.5
  MidLayer1 w0.2: v1(39,38.9) 39.6,38.9 40.3,38.2 40.3,37.731 41.031,37 43.6,37 44.5,36.1 57.5,36.1 59.4,34.2 59.4,24.5 57.2,22.3 55.3,22.3 54.6,23 v1(49.8,23)
  Bottom Layer w0.2: U1.V8@38.5,39.4 v1(39,38.9) ; HDR2.76@44.5,16.5 44.5,21.1 46.4,23 v1(49.8,23)
SPI_CLK: HDR1.46 U1.L4 | length 29.3
  MidLayer1 w0.127: 32.5,44.4 32.5,45.4
  MidLayer1 w0.2: v1(32,43.9) 32.5,44.4 ; 32.5,45.4 v1(32.5,69.8)
  Bottom Layer w0.2: U1.L4@31.5,43.4 v1(32,43.9) ; HDR1.46@32.5,67.3 32.5,69 v1(32.5,69.8)
SPI_DIN: HDR1.44 U1.L3 | length 26.6
  MidLayer1 w0.2: v1(31.7,69) 31.7,60.4 32,60.1 v1(32,44.9)
  Bottom Layer w0.2: U1.L3@31.5,44.4 v1(32,44.9)
  Bottom Layer w0.3: HDR1.44@31.7,67.3 v1(31.7,69)
SPI_DOUT: HDR1.50 U1.M4 | length 29.6
  MidLayer1 w0.127: 33.5,44.4 33.5,45.4
  MidLayer1 w0.2: v1(33,43.9) 33.5,44.4 ; 33.5,45.4 33.5,49.9 33.7,50.1 33.7,66.1 34.1,66.5 v1(34.1,69.8)
  Bottom Layer w0.2: U1.M4@32.5,43.4 v1(33,43.9) ; HDR1.50@34.1,67.3 v1(34.1,69.8)
SPI_MODE: HDR1.52 U1.N4 | length 30.3
  MidLayer1 w0.127: 34.5,43.5 34.5,44.4
  MidLayer1 w0.2: v1(33,42.9) 33.9,42.9 34.5,43.5 ; 34.5,44.4 33.9,45 33.9,49.6 34.1,49.8 34.1,65.3 34.9,66.1 v1(34.9,69)
  Bottom Layer w0.2: v1(33,42.9) U1.N4@33.5,43.4 ; HDR1.52@34.9,67.3 v1(34.9,69)
SPI_SEL: HDR1.48 U1.M3 | length 26.6
  MidLayer1 w0.2: v1(33,44.9) 33,50.1 33.3,50.4 v1(33.3,69)
  Bottom Layer w0.2: U1.M3@32.5,44.4 v1(33,44.9) ; HDR1.48@33.3,67.3 v1(33.3,69)
SRAM0_A0: U1.AA18 U3.5 | length 14.5
  Bottom Layer w0.2: U1.AA18@41.5,29.4 42,28.9 43,28.9 43.6,28.3 49.7,28.3 52.7,25.3 U3.5@54.35,25.3
SRAM0_A1: U1.Y19 U3.4 | length 15.5
  Bottom Layer w0.2: U1.Y19@40.5,28.4 41,27.9 49.5,27.9 52.9,24.5 U3.4@54.35,24.5
SRAM0_A2: U1.AB20 U3.3 | length 13.4
  Bottom Layer w0.2: U1.AB20@42.5,27.4 49.4,27.4 53.075,23.725 U3.3@54.35,23.7 U3.3@54.4,23.7
SRAM0_A3: U1.AA20 U3.2 | length 14.8
  Bottom Layer w0.2: U1.AA20@41.5,27.4 42,26.9 49.2,26.9 53.175,22.925 U3.2@54.35,22.9 U3.2@54.4,22.9
SRAM0_A4: U1.Y20 U3.1 | length 16
  MidLayer1 w0.2: v1(41,26.9) 41.3,26.6 42.3,26.6 42.6,26.3 v1(43.8,26.3)
  Bottom Layer w0.2: U1.Y20@40.5,27.4 v1(41,26.9) ; v1(43.8,26.3) 49.2,26.3 53.4,22.1 U3.1@54.35,22.1
SRAM0_A5: U1.W19 U3.44 | length 29.9
  MidLayer1 w0.2: v1(40,27.9) 40.3,27.6 41.4,27.6 42,27 44.1,27 44.5,26.6 v1(44.5,25.5)
  Bottom Layer w0.2: U1.W19@39.5,28.4 v1(40,27.9) ; v1(44.5,25.5) 49.4,25.5 53.6,21.3 57.2,21.3 58,22.1 U3.44@65.5,22.1
SRAM0_A6: U1.V18 U3.43 | length 29.7
  MidLayer1 w0.127: 39.5,28.4 40.5,28.4
  MidLayer1 w0.2: v1(39,28.9) 39.5,28.4 ; 40.5,28.4 40.8,28.1 41.466,28.1 42.166,27.4 52.2,27.4 v1(56.7,22.9)
  Bottom Layer w0.2: U1.V18@38.5,29.4 v1(39,28.9) ; v1(56.7,22.9) U3.43@65.5,22.9
SRAM0_A7: U1.Y18 U3.42 | length 27.4
  MidLayer1 w0.2: v1(41,28.9) 41.8,28.9 42.9,27.8 52.5,27.8 56.6,23.7 v1(57.2,23.7)
  Bottom Layer w0.2: U1.Y18@40.5,29.4 v1(41,28.9) ; v1(57.2,23.7) U3.42@65.5,23.7
SRAM0_A8: U1.AB11 U3.18 | length 12.1
  Bottom Layer w0.2: U1.AB11@42.5,36.4 52.9,36.4 53.6,35.7 U3.18@54.35,35.7
SRAM0_A9: U1.V9 U3.27 | length 29.6
  MidLayer1 w0.2: v1(39,37.9) 40.7,36.2 43.1,36.2 44.181,35.119 49.981,35.119 50.8,34.3 55.7,34.3 56.1,33.9 57.4,33.9 v1(58,34.1)
  Bottom Layer w0.2: U1.V9@38.5,38.4 v1(39,37.9) ; v1(58,34.1) 59.6,35.7 U3.27@65.5,35.7
SRAM0_A10: U1.AB8 U3.26 | length 24.3
  Bottom Layer w0.2: U1.AB8@42.5,39.4 44,39.4 44.1,39.5 56.1,39.5 59.1,36.5 U3.26@65.5,36.5
SRAM0_A11: U1.AA8 U3.25 | length 25.3
  Bottom Layer w0.2: U1.AA8@41.5,39.4 42,39.9 56.3,39.9 58.9,37.3 U3.25@65.5,37.3
SRAM0_A12: U1.AA6 U3.24 | length 25.6
  Bottom Layer w0.2: U1.AA6@41.5,41.4 42,40.9 42.8,40.9 43.4,40.3 56.5,40.3 59,37.8 64,37.8 64.3,38.1 U3.24@65.5,38.1
SRAM0_A13: U1.Y5 U3.23 | length 27.1
  Bottom Layer w0.2: U1.Y5@40.5,42.4 41,41.9 42.868,41.9 42.968,42 43.7,42 44.5,41.2 45,40.7 56.7,40.7 59.2,38.2 63.8,38.2 64.5,38.9 U3.23@65.5,38.9
SRAM0_A14: U1.W9 U3.22 | length 15.1
  Bottom Layer w0.2: U1.W9@39.5,38.4 40,38.9 U3.22@54.35,38.9
SRAM0_A15: U1.AA10 U3.21 | length 13.1
  Bottom Layer w0.2: U1.AA10@41.5,37.4 41.55,37.45 42,37.9 43.3,37.9 43.5,38.1 U3.21@54.35,38.1
SRAM0_A16: U1.AB10 U3.20 | length 11.9
  Bottom Layer w0.2: U1.AB10@42.5,37.4 53,37.4 53.1,37.3 U3.20@54.35,37.3
SRAM0_A17: U1.Y10 U3.19 | length 14.2
  Bottom Layer w0.2: U1.Y10@40.5,37.4 41,36.9 52.966,36.9 53.366,36.5 U3.19@54.35,36.5
SRAM0_A18: U1.V10 U3.28 | length 29.3
  MidLayer1 w0.2: v1(39,36.9) 39,36.8 40,35.8 42.8,35.8 43.9,34.7 49.731,34.7 49.963,34.469 50.531,33.9 55.4,33.9 55.8,33.5 v1(58.7,33.5)
  Bottom Layer w0.2: U1.V10@38.5,37.4 v1(39,36.9) ; v1(58.7,33.5) 60.1,34.9 U3.28@65.5,34.9
SRAM0_D0: U1.AA17 U3.7 | length 14.3
  Bottom Layer w0.2: U1.AA17@41.5,30.4 42,29.9 42.7,29.9 42.8,29.8 43.5,29.8 44.2,29.1 50.2,29.1 52.4,26.9 U3.7@54.35,26.9
SRAM0_D1: U1.Y17 U3.8 | length 15.5
  Bottom Layer w0.2: U1.Y17@40.5,30.4 41,30.9 42.8,30.9 42.9,31 43.6,31 45.1,29.5 50.5,29.5 52.3,27.7 U3.8@54.35,27.7
SRAM0_D2: U1.Y16 U3.9 | length 15.5
  Bottom Layer w0.2: U1.Y16@40.5,31.4 41,31.9 43.3,31.9 45.3,29.9 50.8,29.9 52.2,28.5 U3.9@54.35,28.5
SRAM0_D3: U1.AB15 U3.10 | length 13.1
  Bottom Layer w0.2: U1.AB15@42.5,32.4 44.7,32.4 45.5,31.6 49.7,31.6 52,29.3 U3.10@54.35,29.3
SRAM0_D4: U1.AA15 U3.13 | length 13.6
  Bottom Layer w0.2: U1.AA15@41.5,32.4 42,32.9 44.9,32.9 45.8,32 52.1,32 52.4,31.7 U3.13@54.35,31.7
SRAM0_D5: U1.AA13 U3.14 | length 13.6
  Bottom Layer w0.2: U1.AA13@41.5,34.4 42,33.9 44.6,33.9 46,32.5 U3.14@54.35,32.5
SRAM0_D6: U1.AB13 U3.15 | length 12.3
  Bottom Layer w0.2: U1.AB13@42.5,34.4 43,34.4 44.7,34.4 45.8,33.3 U3.15@54.35,33.3
SRAM0_D7: U1.Y13 U3.16 | length 14.4
  Bottom Layer w0.2: U1.Y13@40.5,34.4 40.55,34.45 41,34.9 44.9,34.9 45.7,34.1 U3.16@54.35,34.1
SRAM0_D8: U1.U13 U3.29 | length 31.1
  MidLayer1 w0.127: 38.5,35.4 39.5,35.4
  MidLayer1 w0.2: v1(37,34.9) 37.5,35.4 38.5,35.4 ; 39.5,35.4 42.5,35.4 43.6,34.3 49.566,34.3 50.366,33.5 55.1,33.5 55.7,32.9 v1(56.5,32.9)
  Bottom Layer w0.2: v1(37,34.9) U1.U13@37.5,34.4 ; v1(56.5,32.9) 57.2,32.9 57.3,33 58.1,33 58.3,32.8 59.2,32.8 60.5,34.1 U3.29@65.5,34.1
SRAM0_D9: U1.V13 U3.30 | length 28.8
  MidLayer1 w0.2: v1(39,34.9) 42.4,34.9 43.4,33.9 49.4,33.9 50.2,33.1 54.8,33.1 55.7,32.2 56.9,32.2 57.1,32.4 v1(57.7,32.4)
  Bottom Layer w0.2: U1.V13@38.5,34.4 v1(39,34.9) ; v1(57.7,32.4) 59.6,32.4 60.5,33.3 U3.30@65.5,33.3
SRAM0_D10: U1.W13 U3.31 | length 29.3
  MidLayer1 w0.127: 39.5,34.4 41.5,34.4
  MidLayer1 w0.2: v1(39,33.9) 39.5,34.4 ; 41.5,34.4 42.2,34.4 43.1,33.5 49.1,33.5 49.9,32.7 54.6,32.7 55.7,31.6 v1(56.5,31.6)
  Bottom Layer w0.2: v1(39,33.9) U1.W13@39.5,34.4 ; v1(56.5,31.6) 58,31.6 58.2,31.8 62.4,31.8 63.5,32.9 64.3,32.9 64.7,32.5 U3.31@65.5,32.5
SRAM0_D11: U1.W14 U3.32 | length 29
  MidLayer1 w0.127: 40.5,33.4 41.5,33.4
  MidLayer1 w0.2: v1(40,33.9) 40.5,33.4 ; 41.5,33.4 42.2,32.7 48.631,32.7 49.431,31.9 54.2,31.9 55.8,30.3 57,30.3 57.9,29.4 v1(58.7,29.4)
  Bottom Layer w0.2: U1.W14@39.5,33.4 v1(40,33.9) ; v1(58.7,29.4) 59.4,30.1 62.7,30.1 64.3,31.7 U3.32@65.5,31.7
SRAM0_D12: U1.V14 U3.35 | length 29.4
  MidLayer1 w0.2: v1(39,32.9) 39.6,32.3 48.466,32.3 49.266,31.5 54,31.5 v1(56.7,28.8)
  Bottom Layer w0.2: U1.V14@38.5,33.4 v1(39,32.9) ; v1(56.7,28.8) 57.1,28.8 57.4,29.1 58,29.1 58.3,28.8 62.4,28.8 64.1,28.8 64.6,29.3 U3.35@65.5,29.3
SRAM0_D13: U1.U16 U3.36 | length 30.5
  MidLayer1 w0.2: v1(38,30.9) 39,31.9 48.3,31.9 50,30.2 54.4,30.2 56.4,28.2 56.8,28.2 57.1,27.9 v1(58.5,27.9)
  Bottom Layer w0.2: U1.U16@37.5,31.4 v1(38,30.9) ; v1(58.5,27.9) 63.9,27.9 64.5,28.5 U3.36@65.5,28.5
SRAM0_D14: U1.V16 U3.37 | length 29.3
  MidLayer1 w0.2: v1(39,30.9) 39.6,31.5 44,31.5 45.7,29.8 54.2,29.8 56.3,27.7 v1(56.7,27.5)
  Bottom Layer w0.2: U1.V16@38.5,31.4 v1(39,30.9) ; v1(56.7,27.5) 57.7,27.5 57.9,27.3 64.1,27.3 64.5,27.7 U3.37@65.5,27.7
SRAM0_D15: U1.W16 U3.38 | length 28.3
  MidLayer1 w0.2: v1(40,30.9) 42.5,30.9 42.7,31.1 43.6,31.1 45.3,29.4 53.966,29.4 56.7,26.7 v1(57.5,26.7)
  Bottom Layer w0.2: U1.W16@39.5,31.4 v1(40,30.9) ; v1(57.5,26.7) 57.5,26.9 U3.38@65.5,26.9
SRAM0_E: U1.AB18 U3.6 | length 13.2
  Bottom Layer w0.2: U1.AB18@42.5,29.4 43.2,29.4 43.9,28.7 49.9,28.7 52.5,26.1 U3.6@54.35,26.1
SRAM0_LB: U1.V17 U3.39 | length 29.2
  MidLayer1 w0.127: 39.5,30.4 40.5,30.4
  MidLayer1 w0.2: v1(39,29.9) 39.5,30.4 ; 40.5,30.4 41.997,30.4 43.397,29 53.8,29 v1(56.7,26.1)
  Bottom Layer w0.2: U1.V17@38.5,30.4 v1(39,29.9) ; v1(56.7,26.1) U3.39@65.5,26.1
SRAM0_OE: TP1.1 U1.W18 U3.41 | length 36.7
  MidLayer1 w0.127: 40.5,29.4 41.5,29.4
  MidLayer1 w0.2: v1(40,28.9) 40.5,29.4 ; 41.5,29.4 41.866,29.4 43.066,28.2 53,28.2 v1(56.7,24.5)
  Bottom Layer w0.2: U1.W18@39.5,29.4 v1(40,28.9) ; v1(56.7,24.5) U3.41@65.5,24.5 66.6,24.5 66.9,24.2 66.9,19.4 TP1.1@65.5,18
SRAM0_UB: U1.W17 U3.40 | length 28.1
  MidLayer1 w0.2: v1(40,29.9) 41.931,29.9 43.231,28.6 53.166,28.6 56.466,25.3 v1(57.2,25.3)
  Bottom Layer w0.2: U1.W17@39.5,30.4 v1(40,29.9) ; v1(57.2,25.3) 58.4,25.3 U3.40@65.5,25.3
SRAM0_W: TP6.1 U1.W10 U3.17 | length 19.5
  Bottom Layer w0.2: U1.W10@39.5,37.4 40,36.9 40,36.1 40.2,35.9 52.7,35.9 53.19,35.41 53.19,35.21 53.5,34.9 U3.17@54.35,34.9 55.225,34.9 56.5,34.9 TP6.1@57,35 TP6.1@57.4,34.9
SRAM1_A0: U1.D11 U4.5 | length 23.9
  MidLayer1 w0.2: v1(5.2,42.3) 12.2,35.3 20.9,35.3 21.5,35.9 v1(24,35.9)
  Bottom Layer w0.2: U4.5@3.925,42.3 v1(5.2,42.3) ; v1(24,35.9) U1.D11@24.5,36.4
SRAM1_A1: U1.E12 U4.4 | length 27.7
  MidLayer1 w0.127: 23.5,35.4 24.5,35.4
  MidLayer1 w0.2: v1(2.6,41.5) 2.607,41.493 5.307,41.493 11.9,34.9 20.9,34.9 21.1,34.9 21.7,35.5 23.4,35.5 23.5,35.4 ; 24.5,35.4 v1(25,35.9)
  Bottom Layer w0.2: v1(2.6,41.5) U4.4@3.925,41.5 ; v1(25,35.9) U1.E12@25.5,35.4
SRAM1_A2: U1.D13 U4.3 | length 23.6
  MidLayer1 w0.127: 21.5,34.4 23.5,34.4
  MidLayer1 w0.2: v1(5.2,40.7) 11.5,34.4 21.5,34.4 ; 23.5,34.4 v1(24,34.9)
  Bottom Layer w0.2: U4.3@3.925,40.7 v1(5.2,40.7) ; v1(24,34.9) U1.D13@24.5,34.4
SRAM1_A3: U1.C13 U4.2 | length 24.9
  MidLayer1 w0.2: v1(2.6,39.9) 5.3,39.9 11.3,33.9 v1(23,33.9)
  Bottom Layer w0.2: v1(2.6,39.9) U4.2@3.925,39.9 ; v1(23,33.9) U1.C13@23.5,34.4
SRAM1_A4: U1.E17 U4.1 | length 29
  Top Layer w0.2: v1(17.7,30.8) 18.4,31.5 20.8,31.5 21,31.3 25.6,31.3 v1(26,30.9)
  MidLayer1 w0.2: v1(10.4,31.6) 16.9,31.6 v1(17.7,30.8)
  Bottom Layer w0.2: U4.1@3.925,39.1 5.1,39.1 5.4,38.8 5.4,36.3 6.8,34.9 7.1,34.6 7.1,33.3 8.8,31.6 v1(10.4,31.6) ; U1.E17@25.5,30.4 v1(26,30.9)
SRAM1_A5: U1.B10 U4.44 | length 8.1
  Bottom Layer w0.2: U4.44@15.075,39.1 16.934,39.1 18.134,37.9 22,37.9 U1.B10@22.5,37.4
SRAM1_A6: U1.F9 U4.43 | length 15.5
  MidLayer1 w0.2: v1(13.7,39.1) 21.6,39.1 22.3,39.8 25.1,39.8 25.7,39.2 v1(26,38.9)
  Bottom Layer w0.2: v1(13.7,39.1) 14.2,39.9 U4.43@15.075,39.9 U4.43@15.1,39.9 ; v1(26,38.9) 26.45,38.45 U1.F9@26.5,38.4
SRAM1_A7: U1.F7 U4.42 | length 16.5
  MidLayer1 w0.2: v1(13.2,40) 16.4,40 16.9,39.5 21,39.5 21.8,40.3 25.4,40.3 v1(26,40.9)
  Bottom Layer w0.2: v1(13.2,40) 13.7,40 14.2,40.7 U4.42@15.075,40.7 ; v1(26,40.9) U1.F7@26.5,40.4
SRAM1_A8: U1.A15 U4.18 | length 33.1
  Bottom Layer w0.2: U4.18@3.925,52.7 5.1,52.7 7.9,49.9 7.9,37.8 13.3,32.4 21,32.4 U1.A15@21.5,32.4
SRAM1_A9: U1.A5 U4.27 | length 14.4
  Bottom Layer w0.2: U4.27@15.075,52.7 16.2,52.7 18.7,50.2 18.8,50.1 18.8,44.1 18.8,43.831 20.231,42.4 21,42.4 U1.A5@21.5,42.4
SRAM1_A10: U1.B5 U4.26 | length 15.8
  Bottom Layer w0.2: U4.26@15.075,53.5 16.2,53.5 19.2,50.5 19.2,48.4 19.2,43.997 20.297,42.9 22,42.9 U1.B5@22.5,42.4
SRAM1_A11: U1.A4 U4.25 | length 14.9
  Bottom Layer w0.2: U4.25@15.075,54.3 16.2,54.3 19.6,50.9 19.6,44.163 20.363,43.4 U1.A4@21.5,43.4
SRAM1_A12: U1.B4 U4.24 | length 16.4
  Bottom Layer w0.2: U4.24@15.075,55.1 16.2,55.1 20,51.3 20,44.328 20.428,43.9 22,43.9 U1.B4@22.5,43.4
SRAM1_A13: U1.A3 U4.23 | length 14.8
  Bottom Layer w0.2: U4.23@15.075,55.9 16.2,55.9 20.4,51.7 20.4,45.732 21.436,44.696 21.436,44.464 U1.A3@21.5,44.4
SRAM1_A14: U1.A13 U4.22 | length 34.9
  Bottom Layer w0.2: U4.22@3.925,55.9 5.8,55.9 10.4,51.3 10.4,43.8 9.6,43 9.6,38.866 14.066,34.4 U1.A13@21.5,34.4
SRAM1_A15: U1.B13 U4.21 | length 35.8
  Bottom Layer w0.2: U4.21@3.925,55.1 5.8,55.1 10,50.9 10,44 9.2,43.2 9.2,38.7 14,33.9 22,33.9 U1.B13@22.5,34.4
SRAM1_A16: U1.A14 U4.20 | length 33.4
  Bottom Layer w0.2: U4.20@3.925,54.3 5.1,54.3 8.7,50.7 8.7,38.5 13.8,33.4 20.9,33.4 U1.A14@21.5,33.4
SRAM1_A17: U1.B14 U4.19 | length 34.5
  Bottom Layer w0.2: U4.19@3.925,53.5 5.1,53.5 8.3,50.3 8.3,38.1 13.5,32.9 22,32.9 U1.B14@22.5,33.4
SRAM1_A18: U1.B6 U4.28 | length 15.3
  Bottom Layer w0.2: U4.28@15.075,51.9 16.2,51.9 18.4,49.7 18.4,43.666 20.066,42 21.1,42 21.2,41.9 22,41.9 U1.B6@22.5,41.4
SRAM1_D0: U1.D10 U4.7 | length 23.7
  MidLayer1 w0.2: v1(5.2,43.9) 12,37.1 22.6,37.1 22.8,36.9 v1(24,36.9)
  Bottom Layer w0.2: U4.7@3.925,43.9 v1(5.2,43.9) ; v1(24,36.9) U1.D10@24.5,37.4
SRAM1_D1: U1.E10 U4.8 | length 27.7
  MidLayer1 w0.127: 23.5,37.4 24.5,37.4
  MidLayer1 w0.2: v1(2.6,44.7) 5.2,44.7 12.4,37.5 23.4,37.5 23.5,37.4 ; 24.5,37.4 v1(25,37.9)
  Bottom Layer w0.2: v1(2.6,44.7) U4.8@3.925,44.7 ; v1(25,37.9) U1.E10@25.5,37.4
SRAM1_D2: U1.D9 U4.9 | length 23.9
  MidLayer1 w0.2: v1(5.2,45.5) 12.7,38 23,38 23.1,37.9 v1(24,37.9)
  Bottom Layer w0.2: U4.9@3.925,45.5 v1(5.2,45.5) ; v1(24,37.9) U1.D9@24.5,38.4
SRAM1_D3: U1.E9 U4.10 | length 27.9
  MidLayer1 w0.127: 22.5,38.4 24.5,38.4
  MidLayer1 w0.2: v1(2.6,46.3) 5.5,46.3 13.4,38.4 22.5,38.4 ; 24.5,38.4 v1(25,38.9)
  Bottom Layer w0.2: v1(2.6,46.3) U4.10@3.925,46.3 ; v1(25,38.9) U1.E9@25.5,38.4
SRAM1_D4: U1.E14 U4.13 | length 37
  MidLayer1 w0.127: 23.5,33.4 24.5,33.4
  MidLayer1 w0.2: v1(9.4,32.2) 9.5,32.2 9.9,32.6 11.2,32.6 11.6,32.2 19.2,32.2 20.3,33.3 23.4,33.3 23.5,33.4 ; 24.5,33.4 v1(25,33.9)
  Bottom Layer w0.2: U4.13@3.925,48.7 5.5,48.7 5.9,48.3 5.9,36.4 9.4,32.9 v1(9.4,32.2) ; v1(25,33.9) 25.45,33.45 U1.E14@25.5,33.4
SRAM1_D5: U1.A18 U4.14 | length 32.9
  Bottom Layer w0.2: U4.14@3.925,49.5 5.5,49.5 6.3,48.7 6.3,36.7 13.6,29.4 U1.A18@21.5,29.4
SRAM1_D6: U1.B17 U4.15 | length 34.3
  Bottom Layer w0.2: U4.15@3.925,50.3 5.4,50.3 6.7,49 6.7,36.9 13.7,29.9 22,29.9 U1.B17@22.5,30.4
SRAM1_D7: U1.C17 U4.16 | length 35.2
  Bottom Layer w0.2: U4.16@3.925,51.1 5.2,51.1 7.1,49.2 7.1,37.1 12.8,31.4 20.7,31.4 21.2,30.9 23,30.9 U1.C17@23.5,30.4
SRAM1_D8: U1.C7 U4.29 | length 16.4
  Bottom Layer w0.2: U4.29@15.075,51.1 16.2,51.1 18,49.3 18,43.5 20.1,41.4 20.1,41.218 ; 20.091,41.209 20.5,40.8 21.1,40.8 21.2,40.9 23,40.9 U1.C7@23.5,40.4
SRAM1_D9: U1.B8 U4.30 | length 15.9
  Bottom Layer w0.2: U4.30@15.075,50.3 16.2,50.3 17.6,48.9 17.6,42.1 19.8,39.9 22,39.9 U1.B8@22.5,39.4
SRAM1_D10: U1.A8 U4.31 | length 15.1
  Bottom Layer w0.2: U4.31@15.075,49.5 16.1,49.5 17.2,48.4 17.2,40.7 18.5,39.4 U1.A8@21.5,39.4
SRAM1_D11: U1.B9 U4.32 | length 16.1
  Bottom Layer w0.2: U4.32@15.075,48.7 16.1,48.7 16.8,48 16.8,40.4 18.3,38.9 22,38.9 U1.B9@22.5,38.4
SRAM1_D12: U1.A9 U4.35 | length 13.1
  Bottom Layer w0.2: U4.35@15.075,46.3 16.1,46.3 16.4,46 16.4,40.2 18.2,38.4 U1.A9@21.5,38.4
SRAM1_D13: U1.D5 U4.36 | length 13.3
  MidLayer1 w0.127: 22.5,43.4 23.5,43.4
  MidLayer1 w0.2: v1(13.8,45.5) 18.9,45.5 21,43.4 22.5,43.4 ; 23.5,43.4 v1(24,42.9)
  Bottom Layer w0.2: v1(13.8,45.5) U4.36@15.075,45.5 ; v1(24,42.9) 24.45,42.45 U1.D5@24.5,42.4
SRAM1_D14: U1.C5 U4.37 | length 12.9
  MidLayer1 w0.2: v1(13.3,44.7) 19.1,44.7 20.9,42.9 v1(23,42.9)
  Bottom Layer w0.2: v1(13.3,44.7) U4.37@15.075,44.7 ; v1(23,42.9) U1.C5@23.5,42.4
SRAM1_D15: U1.D6 U4.38 | length 13
  MidLayer1 w0.127: 22.5,42.4 23.5,42.4
  MidLayer1 w0.2: v1(13.8,43.9) 19.334,43.9 20.834,42.4 22.5,42.4 ; 23.5,42.4 v1(24,41.9)
  Bottom Layer w0.2: v1(13.8,43.9) U4.38@15.075,43.9 ; v1(24,41.9) U1.D6@24.5,41.4
SRAM1_E: U1.E11 U4.6 | length 27.9
  MidLayer1 w0.127: 23.5,36.4 24.5,36.4
  MidLayer1 w0.2: v1(2.6,43.1) 5.434,43.1 12.734,35.8 20.6,35.8 21.2,36.4 23.5,36.4 ; 24.5,36.4 v1(25,36.9)
  Bottom Layer w0.2: v1(2.6,43.1) U4.6@3.925,43.1 ; v1(25,36.9) U1.E11@25.5,36.4
SRAM1_LB: U1.C6 U4.39 | length 13
  MidLayer1 w0.2: v1(13.2,43.2) 19.4,43.2 20.6,42 21.8,42 21.9,41.9 v1(23,41.9)
  Bottom Layer w0.2: v1(13.2,43.2) 14.1,43.2 14.2,43.1 U4.39@15.075,43.1 ; v1(23,41.9) U1.C6@23.5,41.4
SRAM1_OE: TP2.1 U1.D7 U4.41 | length 13.8
  MidLayer1 w0.2: TP2.1@13.3,41.3 18.4,41.3 19.3,40.4 21.3,40.4 21.8,40.9 v1(24,40.9)
  Bottom Layer w0.2: TP2.1@13.3,41.3 13.5,41.5 U4.41@15.075,41.5 ; v1(24,40.9) U1.D7@24.5,40.4
SRAM1_UB: U1.E7 U4.40 | length 14.4
  MidLayer1 w0.127: 22.5,41.4 24.5,41.4
  MidLayer1 w0.2: v1(13.8,42.5) 14.9,42.5 15.7,41.7 19,41.7 19.9,40.8 21.1,40.8 21.6,41.3 22.4,41.3 22.5,41.4 ; 24.5,41.4 v1(25,40.9)
  Bottom Layer w0.2: v1(13.8,42.5) 14,42.5 14.2,42.3 U4.40@15.075,42.3 ; v1(25,40.9) U1.E7@25.5,40.4
SRAM1_W: TP7.1 U1.B15 U4.17 | length 42.1
  Bottom Layer w0.2: TP7.1@4,58 2.5,56.5 2.5,52.2 2.8,51.9 U4.17@3.925,51.9 5.1,51.9 7.5,49.5 7.5,37.4 13,31.9 22,31.9 U1.B15@22.5,32.4
SW0: HDR2.44 U1.L21 | length 10.9
  Bottom Layer w0.2: U1.L21@31.5,26.4 32,25.9 32,23 30.9,21.9 30.9,20.5 31.7,19.7 HDR2.44@31.7,16.5
SW1: HDR2.46 U1.M22 | length 9.2
  Bottom Layer w0.2: HDR2.46@32.5,16.5 32.5,19.9 32.1,20.3 32.1,22.2 32.5,22.6 U1.M22@32.5,25.4
SW2: HDR2.48 U1.M21 | length 10.2
  Bottom Layer w0.2: U1.M21@32.5,26.4 33,25.9 33,22.1 33.3,21.8 HDR2.48@33.3,16.5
